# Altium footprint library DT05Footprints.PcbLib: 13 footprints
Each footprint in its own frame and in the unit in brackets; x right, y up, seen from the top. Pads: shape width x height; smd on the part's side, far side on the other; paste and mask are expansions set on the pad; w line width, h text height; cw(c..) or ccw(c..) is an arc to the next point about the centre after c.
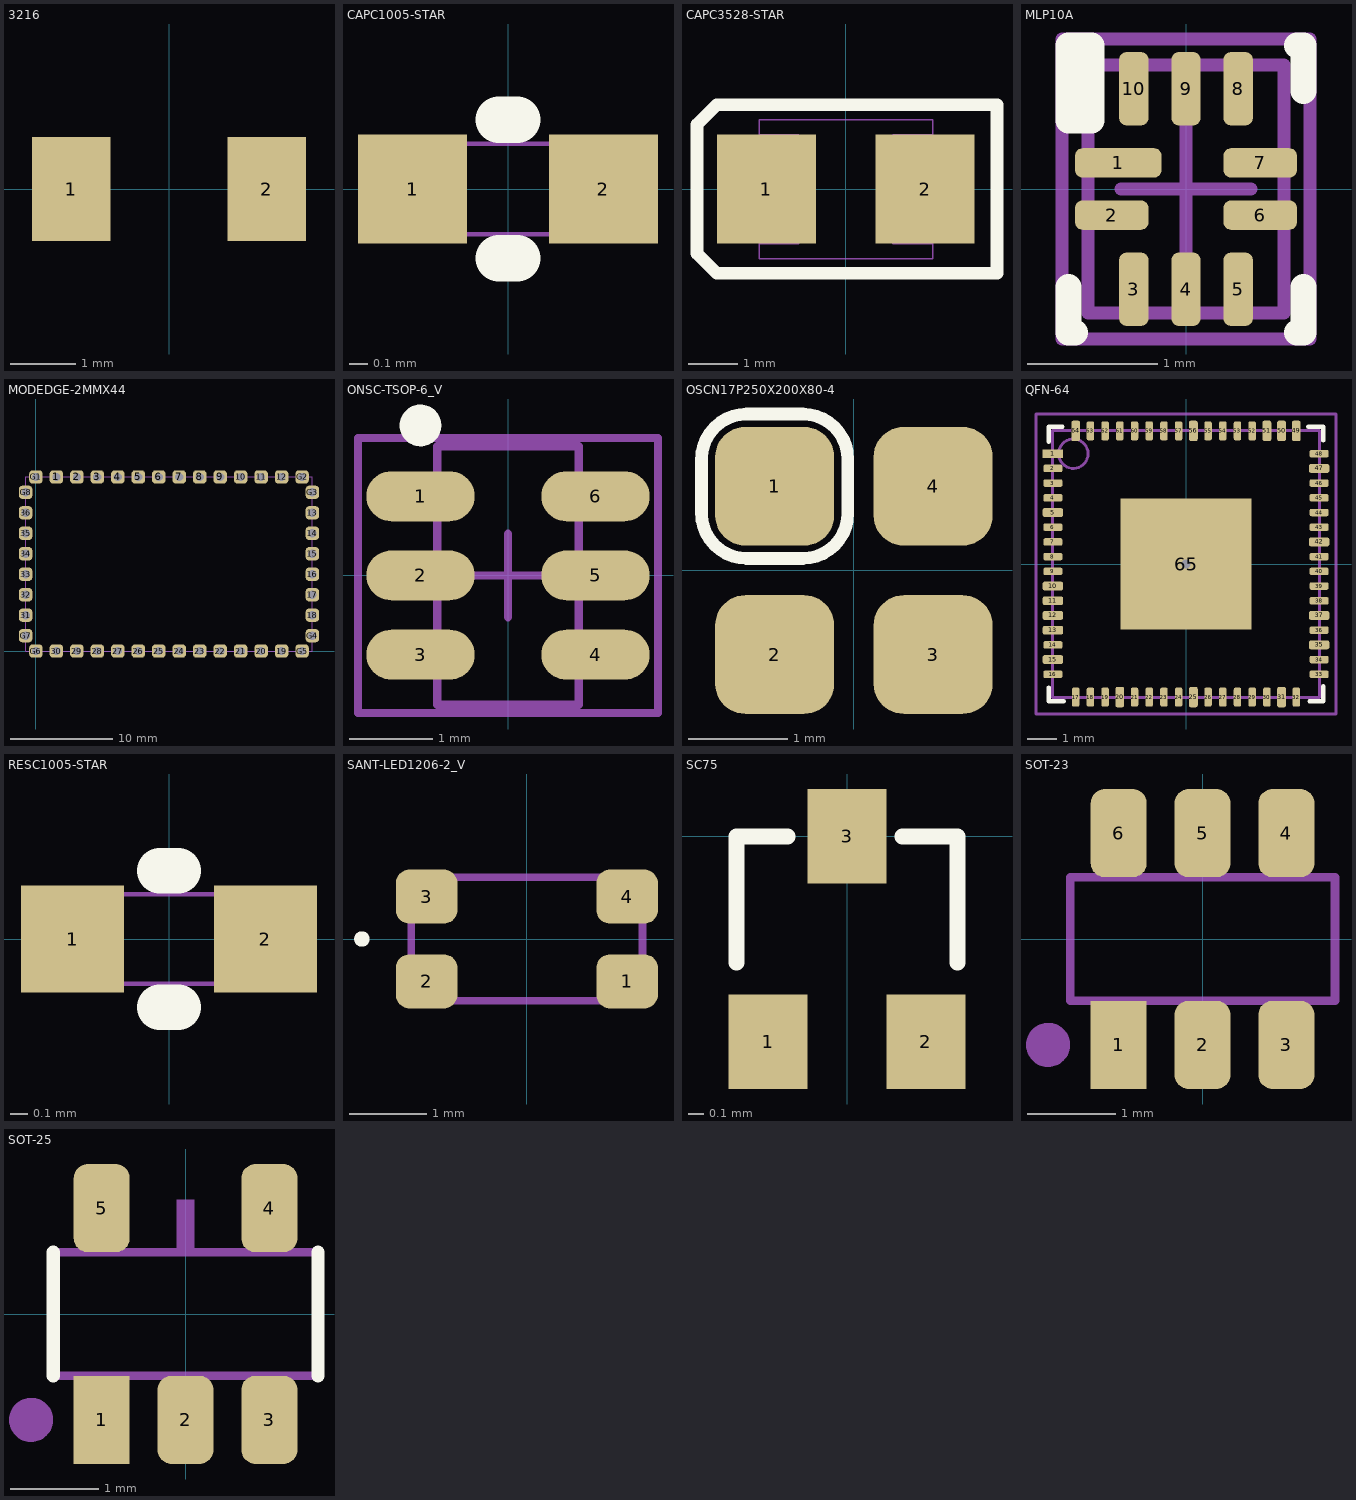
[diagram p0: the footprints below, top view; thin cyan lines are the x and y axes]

## 3216 [mm] "3216 Chip Inductor"
height 0.55
pads (2):
  rect 1.2x1.6 smd paste+0.038 mask+0.038: 1(-1.5,0) 2(1.5,0)
3D body: height 0.25, standoff 0, extent -1.634,-0.254 -1.38,0.254
3D body: height 0.25, standoff 0, extent 1.393,-0.26 1.647,0.248
3D body: height 1.45, standoff 0.94, extent -1.507,-0.774 1.52,0.725
3D body: height 1.19, standoff 0, extent 0.92,-0.774 1.514,0.725
3D body: height 1.19, standoff 0, extent -1.507,-0.755 -0.912,0.744
3D body: height 1.4, standoff 0.13, extent -1.349,-0.69 1.445,0.575

## CAPC1005-STAR [mm] "Chip Capacitor 1005"
height 0.014
pads (2):
  rect 0.6x0.6 smd paste+0.038 mask+0: 1(-0.525,0)
  rect 0.6x0.6 smd paste+0.038 mask+0.038: 2(0.525,0)
Top Overlay:
  lines w0.254: -0.051,-0.381 0.051,-0.381 ; -0.051,0.381 0.051,0.381
Mechanical 8:
  lines w0.025: -0.5,-0.25 -0.5,0.25 0.5,0.25 0.5,-0.25 -0.5,-0.25
  text ".Designator" at -0.475,0.075 h0.14
  text ".Comment" at -0.475,-0.2 h0.14
3D body: height 0.1, standoff 0, extent 0.255,-0.253 0.762,0.253
3D body: height 0.1, standoff 0, extent -0.762,-0.247 -0.254,0.262
3D body: height 0.13, standoff 0, extent -0.262,-0.253 0.255,0.258

## CAPC3528-STAR [mm] "Capacitor 3.5x2.8mm B-Case"
height 2.1
pads (2):
  rect 2x2.2 smd paste+0.038 mask+0.038: 1(-1.6,0)
  rect 2x2.2 smd paste+0.038 mask+0: 2(1.6,0)
Top Overlay:
  lines w0.254: -3,-1.3 -2.6,-1.7 3.05,-1.7 3.05,1.7 -2.6,1.7 -3,1.3 -3,-1.3
Mechanical 8:
  lines w0.025: -1.748,-1.104 -0.948,-1.104 -0.948,1.096 -1.748,1.096 ; 1.752,-1.104 0.952,-1.104 0.952,1.096 1.752,1.096 ; -1.748,-1.404 1.752,-1.404 1.752,1.396 -1.748,1.396 -1.748,-1.404
  text ".Designator" at -1.8,1.8 h0.5
  text ".Comment" at -1.7,-2.2 h0.5
3D body: height 1.96, standoff 0, extent -1.814,-1.397 1.814,1.41

## MLP10A [mm] "QFN, 10-Leads, Body 1.8 x 1.4 mm, Pitch 0.4mm, FSC Recommended"
height 0.55
pads (10):
  rrect50% 0.663x0.225 smd mask+0.038: 1(-0.519,0.2)
  rrect50% 0.563x0.225 smd mask+0.038: 2(-0.569,-0.2) 6(0.569,-0.2) 7(0.569,0.2)
  rrect50% 0.225x0.563 smd mask+0.038: 3(-0.4,-0.768) 4(0,-0.768) 5(0.4,-0.768) 8(0.4,0.768) 9(0,0.768) 10(-0.4,0.768)
Top Overlay:
  lines w0.2: -0.9,-0.75 -0.9,-1.1 -0.85,-1.1 ; -0.9,0.75 -0.9,1.1 ; -0.85,1.1 -0.9,1.1 ; 0.85,-1.1 0.9,-1.1 0.9,-0.75 ; 0.85,1.1 0.9,1.1 0.9,0.75 ; -0.9,1.1 -0.9,0.527 -0.724,0.527 -0.724,1.1 -0.9,1.1
Mechanical 13:
  lines w0.1: -0.75,-0.95 0.75,-0.95 0.75,0.95 -0.75,0.95 -0.75,-0.95
Mechanical 15:
  lines w0.1: -0.5,0 0.5,0 ; 0,-0.5 0,0.5 ; -0.95,-1.15 0.95,-1.15 0.95,1.15 -0.95,1.15 -0.95,-1.15
3D body: height 0.55, standoff 0, extent -0.75,-0.95 0.75,0.95
3D body: height 0.63, standoff 0.58, extent -0.737,0.383 -0.197,0.94

## MODEDGE-2MMX44 [mm] "44 position header connector right angle"
height 13
pads (44):
  rrect50% 1.3x1.3 hole 0.8 paste+0 mask+0: 1(2,17) 2(4,17) 3(6,17) 4(8,17) 5(10,17) 6(12,17) 7(14,17) 8(16,17) 9(18,17) 10(20,17) 11(22,17) 12(24,17) 13(27,13.5) 14(27,11.5) 15(27,9.5) 16(27,7.5) 17(27,5.5) 18(27,3.5) 19(24,0) 20(22,0) 21(20,0) 22(18,0) 23(16,0) 24(14,0) 25(12,0) 26(10,0) 27(8,0) 28(6,0) 29(4,0) 30(2,0) 31(-1,3.5) 32(-1,5.5) 33(-1,7.5) 34(-1,9.5) 35(-1,11.5) 36(-1,13.5) G1(0,17) G2(26,17) G3(27,15.5) G4(27,1.5) G5(26,0) G6(0,0) G7(-1,1.5) G8(-1,15.5)
Mechanical 3:
  lines w0.025: -1,0 27,0 27,17 -1,17 -1,0

## ONSC-TSOP-6_V [mm] "TSOP, 6-Leads, Body 3.1x1.7mm (max), Pitch 0.95mm, Height 1.1mm"
height 1.1
pads (6):
  oval 1.3x0.6 smd: 1(-1.05,0.95) 2(-1.05,0) 3(-1.05,-0.95) 4(1.05,-0.95) 5(1.05,0) 6(1.05,0.95)
Top Overlay:
  circle w0.25: c-1.05,1.8 r0.125
Mechanical 13:
  lines w0.1: -0.85,-1.55 -0.85,1.55 0.85,1.55 0.85,-1.55 -0.85,-1.55
Mechanical 15:
  lines w0.1: -0.5,0 0.5,0 ; 0,-0.5 0,0.5 ; -1.8,-1.65 -1.8,1.65 1.8,1.65 1.8,-1.65 -1.8,-1.65
3D body: height 1.1, standoff 0.1, extent -0.85,-1.55 0.85,1.55

## OSCN17P250X200X80-4 [mm] "SM Crystal Oscillator, 4-Leads, Body 2.5x2x0.8mm, Pitch 1.7mm"
height 1
pads (4):
  rrect50% 1.2x1.2 smd mask+0.038: 1(-0.8,0.85) 2(-0.8,-0.85) 3(0.8,-0.85) 4(0.8,0.85)
Top Overlay:
  lines w0.127: -1.539,0.578 ccw(c-1.082,0.578) -1.082,0.121 -0.518,0.121 ccw(c-0.518,0.578) -0.061,0.578 -0.061,1.122 ccw(c-0.518,1.122) -0.518,1.579 -1.082,1.579 ccw(c-1.082,1.122) -1.539,1.122 -1.539,0.578
3D body: height 0.92, standoff -0.01, extent -1.016,-1.291 0.983,1.291

## QFN-64 [mm] "64-Pin QFN 0.5 mm Pitch"
height 1
pads (65):
  rect 0.7x0.3 smd mask+0: 1(-4.525,3.75)
  rrect50% 0.65x0.254 smd mask+0.038: 2(-4.525,3.25) 3(-4.525,2.75) 4(-4.525,2.25) 6(-4.525,1.25) 7(-4.525,0.75) 8(-4.525,0.25) 9(-4.525,-0.25) 14(-4.525,-2.75) 16(-4.525,-3.75) 33(4.525,-3.75) 34(4.525,-3.25) 36(4.525,-2.25) 38(4.525,-1.25) 39(4.525,-0.75) 40(4.525,-0.25) 41(4.525,0.25) 43(4.525,1.25) 44(4.525,1.75) 45(4.525,2.25) 46(4.525,2.75) 48(4.525,3.75)
  rrect50% 0.7x0.3 smd mask+0: 5(-4.525,1.75) 10(-4.525,-0.75) 11(-4.525,-1.25) 13(-4.525,-2.25) 15(-4.525,-3.25) 35(4.525,-2.75) 47(4.525,3.25)
  rrect50% 0.7x0.3 smd mask+0.038: 12(-4.525,-1.75) 37(4.525,-1.75) 42(4.525,0.75)
  rrect50% 0.254x0.65 smd mask+0.038: 17(-3.75,-4.525) 18(-3.25,-4.525) 19(-2.75,-4.525) 21(-1.75,-4.525) 22(-1.25,-4.525) 23(-0.75,-4.525) 24(-0.25,-4.525) 26(0.75,-4.525) 27(1.25,-4.525) 28(1.75,-4.525) 29(2.25,-4.525) 30(2.75,-4.525) 32(3.75,-4.525) 52(2.25,4.525) 53(1.75,4.525) 54(1.25,4.525) 55(0.75,4.525) 57(-0.25,4.525) 58(-0.75,4.525) 59(-1.25,4.525) 60(-1.75,4.525) 61(-2.25,4.525) 62(-2.75,4.525) 63(-3.25,4.525)
  rrect50% 0.3x0.7 smd mask+0.038: 20(-2.25,-4.525) 31(3.25,-4.525) 49(3.75,4.525) 50(3.25,4.525) 56(0.25,4.525) 64(-3.75,4.525)
  rrect50% 0.3x0.7 smd mask+0: 25(0.25,-4.525) 51(2.75,4.525)
  rect 4.45x4.45 / inner rect 6x6 / far side rect 2.54x2.54 hole 0.3 paste+0 mask+0: 65(0,0)
Top Overlay:
  lines w0.15: -4.66,-4.2 -4.66,-4.66 -4.16,-4.66 ; -4.66,4.16 -4.66,4.66 -4.2,4.66 ; 4.16,4.66 4.66,4.66 4.66,4.2 ; 4.2,-4.66 4.66,-4.66 4.66,-4.16
Mechanical 13:
  circle w0.1: c-3.83,3.75 r0.5
  lines w0.1: -4.535,-4.535 -4.535,4.535 4.535,4.535 4.535,-4.535 -4.535,-4.535
Mechanical 15:
  lines w0.1: -0.5,0 0.5,0 ; 0,-0.5 0,0.5 ; -5.1,-5.1 -5.1,5.1 5.1,5.1 5.1,-5.1 -5.1,-5.1
3D body: height 0.25, standoff 0, extent 4.318,0.178 4.572,0.33
3D body: height 0.25, standoff 0, extent 4.318,0.686 4.572,0.838
3D body: height 0.25, standoff 0, extent 4.318,1.676 4.572,1.829
3D body: height 0.25, standoff 0, extent 4.318,1.168 4.572,1.321
3D body: height 0.25, standoff 0, extent 4.318,3.175 4.572,3.327
3D body: height 0.25, standoff 0, extent 4.318,3.683 4.572,3.836
3D body: height 0.25, standoff 0, extent 4.318,2.667 4.572,2.82
3D body: height 0.25, standoff 0, extent 4.318,2.159 4.572,2.312
3D body: height 0.25, standoff 0, extent 4.318,-1.829 4.572,-1.676
3D body: height 0.25, standoff 0, extent 4.318,-1.321 4.572,-1.168
3D body: height 0.25, standoff 0, extent 4.318,-0.305 4.572,-0.152
3D body: height 0.25, standoff 0, extent 4.318,-0.813 4.572,-0.66
3D body: height 0.25, standoff 0, extent 4.318,-2.819 4.572,-2.667
3D body: height 0.25, standoff 0, extent 4.318,-2.311 4.572,-2.159
3D body: height 0.25, standoff 0, extent 4.318,-3.302 4.572,-3.149
3D body: height 0.25, standoff 0, extent 4.318,-3.81 4.572,-3.657
3D body: height 0.25, standoff 0, extent -4.572,-3.81 -4.318,-3.658
3D body: height 0.25, standoff 0, extent -4.572,-3.302 -4.318,-3.15
3D body: height 0.25, standoff 0, extent -4.572,-2.311 -4.318,-2.159
3D body: height 0.25, standoff 0, extent -4.572,-2.819 -4.318,-2.667
3D body: height 0.25, standoff 0, extent -4.572,-0.813 -4.318,-0.66
3D body: height 0.25, standoff 0, extent -4.572,-0.305 -4.318,-0.152
3D body: height 0.25, standoff 0, extent -4.572,-1.321 -4.318,-1.168
3D body: height 0.25, standoff 0, extent -4.572,-1.829 -4.318,-1.676
3D body: height 0.25, standoff 0, extent -4.572,2.159 -4.318,2.312
3D body: height 0.25, standoff 0, extent -4.572,2.667 -4.318,2.82
3D body: height 0.25, standoff 0, extent -4.572,3.683 -4.318,3.835
3D body: height 0.25, standoff 0, extent -4.572,3.175 -4.318,3.327
3D body: height 0.25, standoff 0, extent -4.572,1.168 -4.318,1.321
3D body: height 0.25, standoff 0, extent -4.572,1.676 -4.318,1.829
3D body: height 0.25, standoff 0, extent -4.572,0.686 -4.318,0.838
3D body: height 0.25, standoff 0, extent -4.572,0.178 -4.318,0.33
3D body: height 0.25, standoff 0, extent 3.683,4.318 3.835,4.572
3D body: height 0.25, standoff 0, extent 3.175,4.318 3.327,4.572
3D body: height 0.25, standoff 0, extent 2.184,4.318 2.337,4.572
3D body: height 0.25, standoff 0, extent 2.692,4.318 2.845,4.572
3D body: height 0.25, standoff 0, extent 0.686,4.318 0.838,4.572
3D body: height 0.25, standoff 0, extent 0.178,4.318 0.33,4.572
3D body: height 0.25, standoff 0, extent 1.194,4.318 1.346,4.572
3D body: height 0.25, standoff 0, extent 1.702,4.318 1.854,4.572
3D body: height 0.25, standoff 0, extent -2.286,4.318 -2.134,4.572
3D body: height 0.25, standoff 0, extent -2.794,4.318 -2.642,4.572
3D body: height 0.25, standoff 0, extent -3.81,4.318 -3.658,4.572
3D body: height 0.25, standoff 0, extent -3.302,4.318 -3.15,4.572
3D body: height 0.25, standoff 0, extent -1.295,4.318 -1.143,4.572
3D body: height 0.25, standoff 0, extent -1.803,4.318 -1.651,4.572
3D body: height 0.25, standoff 0, extent -0.813,4.318 -0.66,4.572
3D body: height 0.25, standoff 0, extent -0.305,4.318 -0.152,4.572
3D body: height 0.25, standoff 0, extent 3.683,-4.572 3.835,-4.318
3D body: height 0.25, standoff 0, extent 3.175,-4.572 3.327,-4.318
3D body: height 0.25, standoff 0, extent 2.184,-4.572 2.337,-4.318
3D body: height 0.25, standoff 0, extent 2.692,-4.572 2.845,-4.318
3D body: height 0.25, standoff 0, extent 0.686,-4.572 0.838,-4.318
3D body: height 0.25, standoff 0, extent 0.178,-4.572 0.33,-4.318
3D body: height 0.25, standoff 0, extent 1.194,-4.572 1.346,-4.318
3D body: height 0.25, standoff 0, extent 1.702,-4.572 1.854,-4.318
3D body: height 0.25, standoff 0, extent -2.286,-4.572 -2.134,-4.318
3D body: height 0.25, standoff 0, extent -2.794,-4.572 -2.642,-4.318
3D body: height 0.25, standoff 0, extent -3.81,-4.572 -3.658,-4.318
3D body: height 0.25, standoff 0, extent -3.302,-4.572 -3.15,-4.318
3D body: height 0.25, standoff 0, extent -1.295,-4.572 -1.143,-4.318
3D body: height 0.25, standoff 0, extent -1.803,-4.572 -1.651,-4.318
3D body: height 0.25, standoff 0, extent -0.813,-4.572 -0.66,-4.318
3D body: height 0.25, standoff 0, extent -0.305,-4.572 -0.152,-4.318
3D body: height 1, standoff 0.05, extent -4.535,-4.535 4.535,4.535

## RESC1005-STAR [mm] "Chip Resistor 1005"
height 0.014
pads (2):
  rect 0.575x0.6 smd paste+0.038 mask+0.038: 1(-0.538,0) 2(0.538,0)
Top Overlay:
  lines w0.254: -0.051,-0.381 0.051,-0.381 ; -0.051,0.381 0.051,0.381
Mechanical 8:
  lines w0.025: -0.5,-0.25 -0.5,0.25 0.5,0.25 0.5,-0.25 -0.5,-0.25
  text ".Designator" at -0.475,0.075 h0.14
  text ".Comment" at -0.475,-0.2 h0.14
3D body: height 0.1, standoff 0, extent 0.382,-0.253 0.711,0.253
3D body: height 0.1, standoff 0, extent -0.711,-0.253 -0.331,0.253
3D body: height 0.25, standoff 0, extent -0.33,-0.254 0.381,0.254

## SANT-LED1206-2_V [mm] "SMT RGB LED, 4-Leads, Body 3.2x1.5mm (1206-Size)"
pads (4):
  rrect50% 0.8x0.7 smd mask+0.038: 1(1.3,-0.55) 2(-1.3,-0.55) 3(-1.3,0.55) 4(1.3,0.55)
Top Overlay:
  circle w0.1: c-2.14,0 r0.05
Top Paste:
  rectangle: 1.362,-0.539 1.624,-0.46
Top Solder:
  rectangle: 1.309,-0.556 1.649,-0.462
Mechanical 13:
  lines w0.1: -1.5,-0.8 1.5,-0.8 1.5,0.8 -1.5,0.8 -1.5,-0.8
3D body: height 0.26, standoff -0.01, extent -1.464,-0.755 -0.628,-0.245
3D body: height 0.26, standoff -0.01, extent 0.673,-0.75 1.508,-0.24
3D body: height 0.26, standoff -0.01, extent 0.663,0.268 1.498,0.779
3D body: height 0.26, standoff -0.01, extent -1.482,0.252 -0.647,0.763
3D body: height 0.67, standoff 0.17, extent -0.752,0.127 -0.254,0.625
3D body: height 0.67, standoff 0.17, extent 0.261,-0.629 0.758,-0.131
3D body: height 0.67, standoff 0.17, extent 0.261,0.14 0.758,0.638
3D body: height 0.7, standoff 0.2, extent -1.011,-0.735 0,0.745
3D body: height 0.7, standoff 0.2, extent 0,-0.735 1.011,0.745
3D body: height 0.25, standoff 0, extent 0.016,-0.742 1.489,0.76
3D body: height 0.25, standoff 0, extent -1.458,-0.741 0.015,0.761

## SC75 [mm] "SOT416 FOOTPRINT"
pads (3):
  rect 0.5x0.6 smd mask+0.038: 1(-0.5,-1.3) 2(0.5,-1.3) 3(0,0)
Top Overlay:
  lines w0.1: -0.7,-0.8 -0.7,0 -0.375,0 ; 0.35,0 0.7,0 0.7,-0.8
3D body: height 0.38, standoff 0, extent -0.533,-1.195 0.533,0
3D body: height 0.13, standoff 0, extent -0.164,-0.268 0.164,0.232
3D body: height 0.13, standoff 0, extent 0.243,-1.478 0.571,-0.978
3D body: height 0.13, standoff 0, extent -0.585,-1.485 -0.257,-0.985

## SOT-23 [mm] "1.9mm pitch, 3 lead, 1.1mm height"
height 1.1
pads (6):
  rect 0.635x1 smd paste+0 mask+0.038: 1(-0.95,-1.2)
  rrect50% 0.635x1 smd paste+0 mask+0: 2(0,-1.2)
  rrect50% 0.635x1 smd paste+0 mask+0.038: 3(0.95,-1.2) 4(0.95,1.2) 5(0,1.2) 6(-0.95,1.2)
Mechanical 7:
  circle w0.25: c-1.75,-1.2 r0.125
  region: -0.9,-0.7 -1.1,-0.7 -1.1,-1.3 -0.9,-1.3
  region: 0.1,-0.7 -0.1,-0.7 -0.1,-1.3 0.1,-1.3
  region: 1.1,-0.7 0.9,-0.7 0.9,-1.3 1.1,-1.3
  rectangle: 0.9,0.7 1.1,1.3
  rectangle: -0.1,0.7 0.1,1.3
  rectangle: -1.1,0.7 -0.9,1.3
  lines w0.1: -1.5,-0.7 -1.5,0.7 1.5,0.7 1.5,-0.7 -1.5,-0.7
3D body: height 1.09, standoff 0, extent -1.411,-1.245 1.383,1.18

## SOT-25 [mm] "0.95 pitch, 5 lead, 1.0mm height"
height 1.1
pads (5):
  rect 0.635x1 smd paste+0 mask+0.038: 1(-0.95,-1.2)
  rrect50% 0.635x1 smd paste+0 mask+0: 2(0,-1.2)
  rrect50% 0.635x1 smd paste+0 mask+0.038: 3(0.95,-1.2) 4(0.95,1.2) 5(-0.95,1.2)
Top Overlay:
  lines w0.15: -1.5,-0.7 -1.5,0.7 ; 1.5,-0.7 1.5,0.7
Mechanical 7:
  circle w0.25: c-1.75,-1.2 r0.125
  region: -0.9,-0.7 -1.1,-0.7 -1.1,-1.3 -0.9,-1.3
  region: 0.1,-0.7 -0.1,-0.7 -0.1,-1.3 0.1,-1.3
  region: 1.1,-0.7 0.9,-0.7 0.9,-1.3 1.1,-1.3
  rectangle: 0.9,0.7 1.1,1.3
  rectangle: -0.1,0.7 0.1,1.3
  rectangle: -1.1,0.7 -0.9,1.3
  lines w0.1: -1.5,-0.7 -1.5,0.7 1.5,0.7 1.5,-0.7 -1.5,-0.7
3D body: height 0.78, standoff 0, extent -1.45,-1.397 1.45,1.403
